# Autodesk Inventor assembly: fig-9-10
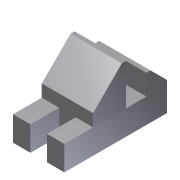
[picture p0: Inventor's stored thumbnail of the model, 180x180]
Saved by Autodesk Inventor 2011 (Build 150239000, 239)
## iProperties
Shininess: 64.0
Length Units: 11269
Angle Units: 11279
Time Units: 11290
Mass Units: 11283
Length Display Precision: 3
Angle Display Precision: 2
Created: 2002-01
Part Number: fig-9-10
Document SubType Name: Assembly
Designer: ***
Density: 0.0
Volumn: 0.0
Area: 0.0
PropertySet Name: Model Information
Control State: 0
Master: False
Checked Out: False
Author: ***
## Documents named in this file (3)
- C:\Users\CADSoft\Desktop\part files\c09-inv-2011-prt\fig-9-10.iam
- C:\Users\CADSoft\Desktop\inventor\c09-inv-2010-prt\c09\Part3.ipt
- C:\Users\CADSoft\Desktop\inventor\c09-inv-2010-prt\c09\Part4.ipt
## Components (2 placed, 2 different names)
1. Part3:1
2. Part4:1
